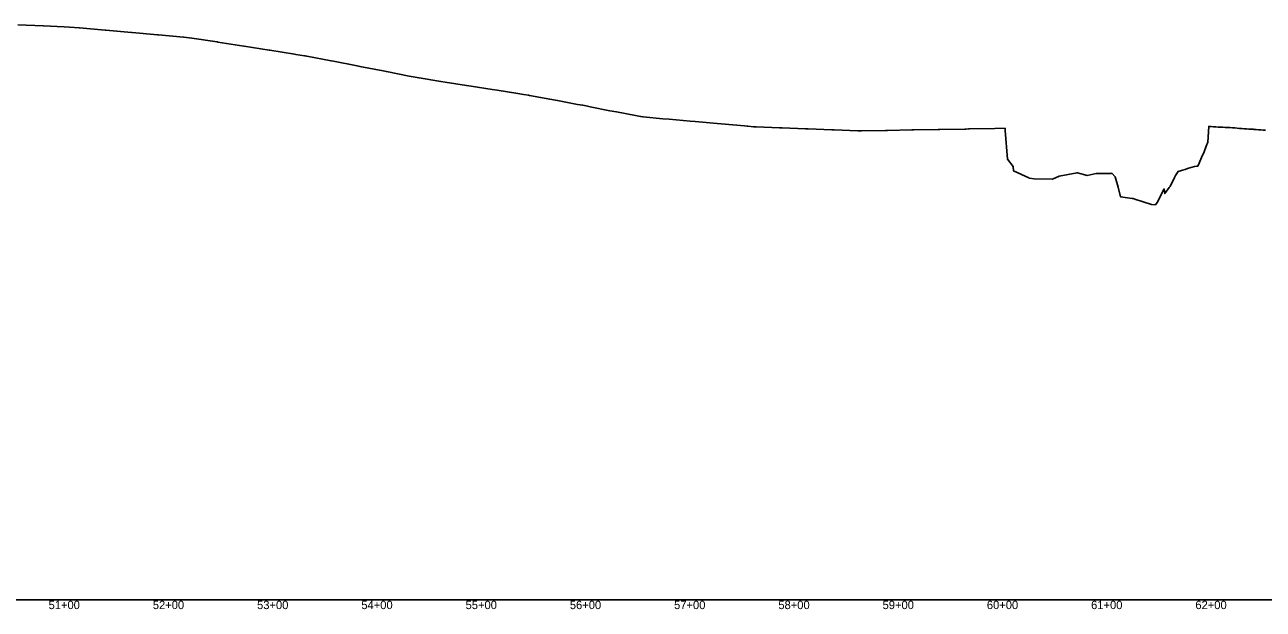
# Model space of a CAD drawing. Extents: x 49922 to 54713, y 49991 to 62800.
# Drawn here: x 51060 to 52247, y 49991 to 50551 of the extents above; entities that cross this region are included whole.
import ezdxf

# ---------------------------------------------------------------- set-up
doc = ezdxf.new("R2010")
doc.units = 0
for name, color, linetype in [('RD_DDB_Profile_EX', 7, 'Continuous'), ('RD_DDB_StaTX', 7, 'Continuous'), ('RD_GPK_Profile_Cell', 7, 'Continuous')]:
    doc.layers.add(name, color=color, linetype=linetype)

msp = doc.modelspace()

# ---------------------------------------------------------------- linework, layer by layer
at = {"layer": 'RD_DDB_Profile_EX'}
for points in [[(51052.9, 50551.2), (51077.1, 50550.1), (51077.6, 50550.1), (51097.5, 50549.2), (51102.4, 50548.9), (51111.8, 50548.4), (51112.2, 50548.4), (51136.8, 50546.1), (51137.4, 50546.1), (51161.8, 50543.8), (51162.6, 50543.8), (51186.8, 50541.6), (51187.8, 50541.5), (51211.8, 50539.3), (51212.2, 50539.2), (51219.7, 50538.5), (51244, 50534.8), (51244.7, 50534.6), (51269.7, 50530.8), (51270, 50530.7), (51294, 50526.9), (51294.7, 50526.8), (51318.3, 50523.1), (51319.7, 50522.8), (51327.9, 50521.5), (51328.4, 50521.5), (51330.1, 50521.1), (51353.4, 50516.6), (51355.6, 50516.2), (51378.4, 50511.8), (51381.1, 50511.3), (51403.4, 50507), (51406.5, 50506.3), (51428.3, 50502.1), (51436.1, 50500.6), (51437.8, 50500.3), (51458.6, 50497), (51462.8, 50496.3), (51483.3, 50493.1), (51487.8, 50492.4), (51507.9, 50489.2), (51512.8, 50488.4), (51532.6, 50485.3), (51537.8, 50484.5), (51542.7, 50483.7), (51543.8, 50483.5), (51563.1, 50479.8), (51568.8, 50478.9), (51570.5, 50478.6), (51589.8, 50474.9), (51594.8, 50474), (51599.4, 50473.2), (51602, 50472.4), (51620.7, 50468.8), (51627.1, 50467.7), (51645.5, 50464.2), (51650.2, 50463.4), (51652.7, 50462.9), (51671.7, 50461.2), (51677.7, 50460.6), (51697.7, 50458.9), (51702.7, 50458.4), (51723.7, 50456.5), (51727.6, 50456.2), (51749.8, 50454.2), (51752.6, 50453.9), (51753, 50453.9), (51758.6, 50453.4), (51761, 50453.3), (51783.6, 50452.4), (51786, 50452.4), (51808.6, 50451.5), (51811.1, 50451.4), (51833.6, 50450.5), (51836.1, 50450.5), (51858.6, 50449.6), (51859.1, 50449.6), (51862.2, 50449.5), (51885.1, 50449.9), (51887.2, 50449.9), (51910.5, 50450.4), (51912.2, 50450.4), (51935.8, 50450.8), (51937.2, 50450.9), (51961.2, 50451.3), (51962.2, 50451.3), (51964.8, 50451.4), (51965.7, 50451.4), (51990, 50451.9), (52000, 50452.2)], [(52000, 50452.2), (52000.1, 50449.8), (52002.1, 50422.3), (52007.6, 50415.5), (52007.8, 50411.2), (52022.6, 50404.5), (52023.1, 50404.2), (52027.7, 50403.5), (52045.5, 50403.2), (52051.8, 50406), (52068.9, 50409.4), (52069.3, 50409.4), (52078.6, 50406.6), (52087.1, 50408.6), (52090, 50408.7), (52101.6, 50408.8), (52102.2, 50408.9), (52105.4, 50405.3), (52108.5, 50395.5), (52110.7, 50386.2), (52121.9, 50384.7), (52122.7, 50384.6), (52124.3, 50384.1), (52140.4, 50379), (52144.1, 50378.6), (52145.6, 50380.9), (52152.5, 50393.9), (52153.1, 50389.4), (52157.4, 50395.2), (52158.3, 50396.2), (52162.3, 50404.8), (52163.4, 50406.6), (52166, 50410.6), (52166.7, 50410.8), (52168, 50411.2), (52170.2, 50411.9), (52172.5, 50412.6), (52174.8, 50413.3), (52177, 50414), (52179.3, 50414.7), (52181.6, 50415.3), (52183.9, 50415.7), (52184.9, 50415.8), (52186.1, 50418.7), (52188.4, 50424.1), (52190.7, 50429.5), (52192.9, 50434.9), (52194.5, 50438.7), (52195.2, 50453.8), (52197.5, 50453.6), (52199.7, 50453.5), (52202, 50453.4), (52204.3, 50453.2), (52206.6, 50453.1), (52208.8, 50453), (52211.1, 50452.8), (52213.4, 50452.7), (52215.6, 50452.6), (52217.9, 50452.4), (52219.3, 50452.3), (52220.2, 50452.3), (52222.4, 50452.1), (52224.7, 50451.9), (52227, 50451.8), (52229.3, 50451.6), (52231.5, 50451.5), (52233.8, 50451.3), (52236.1, 50451.1), (52238.3, 50451), (52238.6, 50450.9), (52240.6, 50450.7), (52242.9, 50450.6), (52245.1, 50450.4), (52247.4, 50450.2), (52249.7, 50450.1)]]:
    msp.add_lwpolyline(points, dxfattribs=at)
at = {"layer": 'RD_GPK_Profile_Cell'}
msp.add_line((50000, 50000), (54600, 50000), dxfattribs=at)

# ---------------------------------------------------------------- texts
at = {"layer": 'RD_DDB_StaTX'}
for s, p in [('51+00', (51082.4, 49991)), ('52+00', (51182.4, 49991)), ('53+00', (51282.4, 49991)), ('54+00', (51382.4, 49991)), ('55+00', (51482.4, 49991)), ('56+00', (51582.4, 49991)), ('57+00', (51682.4, 49991)), ('58+00', (51782.4, 49991)), ('59+00', (51882.4, 49991)), ('60+00', (51982.4, 49991)), ('61+00', (52082.4, 49991)), ('62+00', (52182.4, 49991))]:
    msp.add_text(s, height=8, dxfattribs=at).set_placement(p)

doc.saveas('drawing.dxf')
